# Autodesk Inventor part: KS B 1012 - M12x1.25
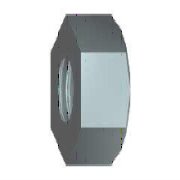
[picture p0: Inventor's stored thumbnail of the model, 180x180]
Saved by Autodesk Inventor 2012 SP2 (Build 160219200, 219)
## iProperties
IsCustomPart: 0
Created: 2009-02
Part Number: KS B 1012 - M12x1.25
Material: 강, 연강
Description: 6각 너트
Document SubType Name: Modeling
Standard: KS B 1012
Designer: KYOUNG IL JANG
Standards Organization: KS
Language: ko-KR
Size Designation: M12x1.25
Categories: <MemberInstance><Categories><Category DisplayName="조임쇠" InternalName="e4da775c-781d-43d5-af7c-5136215cf5a6" Mnemonic="FSTN"><Category DisplayName="너트" InternalN
Density: 1 g/cm^3
Author: KYOUNG IL JANG
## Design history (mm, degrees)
body "Solid1"
sketch "스케치1"
  geometry: L1 (10.97, 0)-(5.485, -9.5); L2 (5.485, -9.5)-(-5.485, -9.5); L3 (-5.485, -9.5)-(-10.97, 0); L4 (-10.97, 0)-(-5.485, 9.5); L5 (-5.485, 9.5)-(5.485, 9.5); L6 (5.485, 9.5)-(10.97, 0); 2 further points
  constraints: 12 end point, 1 coincident, 1 horizontal, 11 other
  dimensions: "d0" = 21.93931 distance of L1.start L3.end (= 1.1547 x SW)
extrude "본체" new body sketch "스케치1" distance "d1" = 10 (= KOH); taper "d2" = 0 deg
revolve "모따기3" stored, may be unused: angle "d5" = 90 deg
sketch "스케치2"
  geometry: 1 further point
hole "스레드" sketch "스케치2" diameter "d6" = 10.647; stored, may be unused: countersink angle "d10" = 82 deg, drill point angle "d12" = 118 deg; dims "d7" = 12.7, "d8" = 9.525, "d9" = 6.35, "d11" = 19.05
workaxis "Work Axis1"
workplane "Work Plane1"
chamfer "모따기1" distance "d13" = 0.67658 (= -0.5 x GD1 + 0.5 x NND); stored, may be unused: angle "d14" = 30 deg, second distance "d21" = 0.67658 (= -0.5 x GD1 + 0.5 x NND)
chamfer "모따기2" distance "d15" = 0.67658 (= -0.5 x GD1 + 0.5 x NND); stored, may be unused: angle "d16" = 30 deg, second distance "d22" = 0.67658 (= -0.5 x GD1 + 0.5 x NND)
sketch "스케치3"
  geometry: L1 (0, 10.97)-(10, 10.97) reference; L2 (10, 5.485)-(10, 10.97) reference; L3 (-2, 0)-(12, 0) reference; L4 (9.151, 10.97)-(10, 9.5)
  constraints: 2 end point, 2 point on line
  dimensions: "d3" = 19 diameter of L4.end L3 (= SW01); "d4" = 30 deg angle of L2 L4 (= ANG2)
other parameters: "ANG2" = 30 deg [user parameter; used in 1 equation term], "NND" = 12 [user parameter; used in 4 equation terms], "KOH" = 10 [user parameter; used in 1 equation term], "SW" = 19 [user parameter; used in 3 equation terms], "SW01" = 19 (= SW) [user parameter; used in 1 equation term], "GD1" = 10.64684 (computed from THREADDIA, PTC, TOA) [user parameter; used in 4 equation terms], "d19" = 0, "d20" = 0, "d24" = 0, "d25" = 0, "GUL" = 0.67658 (= 0.541266 x PTC) [user parameter], "TPU" = 8 (computed from PTC) [user parameter], "TOA" = 30 deg [user parameter; used in 1 equation term], "PTC" = 1.25 [user parameter; used in 4 equation terms], "E0" = 21.945 (= 1.155 x SW) [user parameter], "THREADDIA" = 12 [user parameter; used in 1 equation term], "GAL" = 0.67658 (= 0.541266 x PTC) [user parameter]
